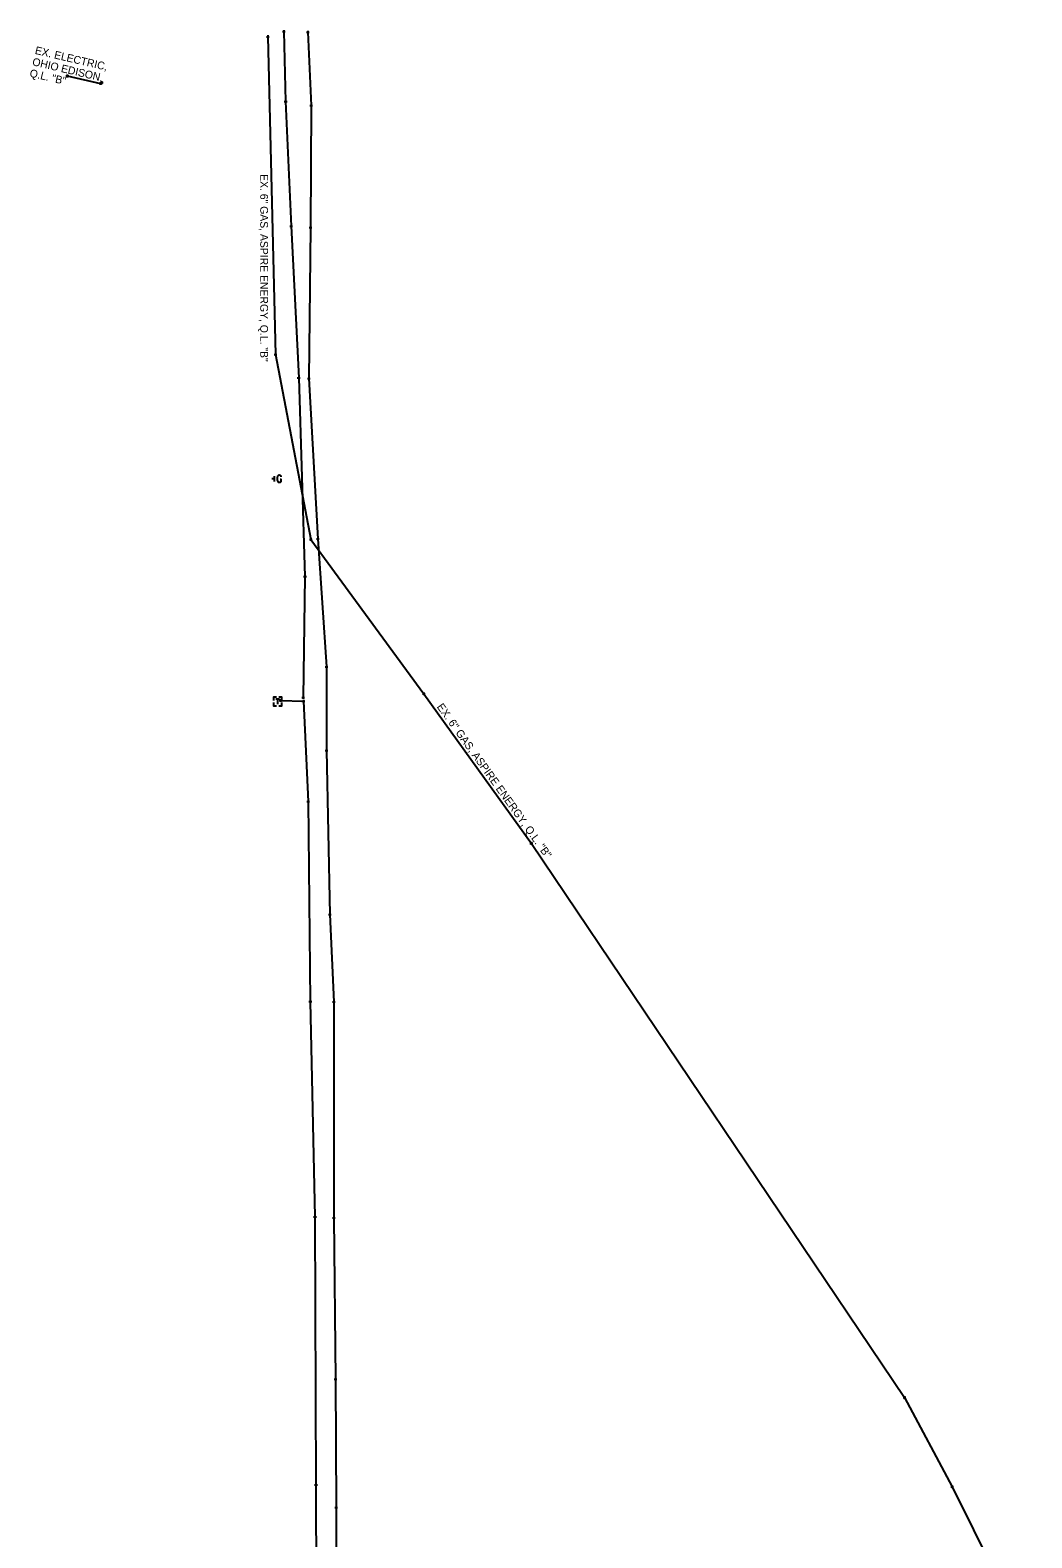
# Model space of a CAD drawing. Extents: x 2046588 to 2048646, y 455919 to 457871.
# Drawn here: x 2047559 to 2047919, y 457329 to 457871 of the extents above; entities that cross this region are included whole.
import ezdxf

# ---------------------------------------------------------------- set-up
doc = ezdxf.new("R2010")
doc.units = 0
for name, color, linetype in [('CM_Corridor_Top_Mesh', 7, 'Continuous'), ('DR_P_Text', 7, 'Continuous'), ('MD_P_Surface_Curb', 7, 'Continuous'), ('PF_P_Grade_Line', 7, 'Continuous'), ('UT_P_Gas', 7, 'Continuous'), ('UT_X_FO', 7, 'Continuous'), ('UT_X_Gas', 7, 'Continuous'), ('UT_X_Overhead_Combined', 7, 'Continuous'), ('UT_X_Overhead_Telecom', 7, 'Continuous')]:
    doc.layers.add(name, color=color, linetype=linetype)

msp = doc.modelspace()

# ---------------------------------------------------------------- linework, layer by layer
at = {"layer": 'CM_Corridor_Top_Mesh'}
for points in [[(2047649.99, 457870.5), (2047650.66, 457845.3), (2047652.68, 457800.52), (2047655.35, 457745.96), (2047657.6, 457674.47), (2047656.94, 457631.01)], [(2047648.82, 457629.87), (2047657.02, 457629.62), (2047658.75, 457593.58), (2047659.52, 457521.71), (2047661.21, 457444.24), (2047661.57, 457347.82), (2047661.76, 457274.75), (2047663.01, 457236.05), (2047662.63, 457177.6), (2047665.24, 457077.73), (2047667.68, 457023.38), (2047665.85, 457013.41)]]:
    msp.add_lwpolyline(points, dxfattribs=at)
at = {"layer": 'PF_P_Grade_Line'}
msp.add_lwpolyline([(2047572.16, 457854.53), (2047584.07, 457851.83), (2047584.5, 457852.13)], dxfattribs=at)
at = {"layer": 'UT_P_Gas'}
for p, q in [((2047647.16, 457630.55), (2047648.46, 457630.55)), ((2047647.81, 457628.55), (2047647.81, 457630.55)), ((2047647.81, 457629.55), (2047647.81, 457629.55))]:
    msp.add_line(p, q, dxfattribs=at)
for points in [[(2047647.41, 457631.05), (2047646.31, 457631.05), (2047646.31, 457629.95)], [(2047646.31, 457629.15), (2047646.31, 457628.05), (2047647.41, 457628.05)], [(2047649.31, 457629.95), (2047649.31, 457631.05), (2047648.21, 457631.05)], [(2047648.21, 457628.05), (2047649.31, 457628.05), (2047649.31, 457629.15)]]:
    msp.add_lwpolyline(points, dxfattribs=at)
at = {"layer": 'UT_X_FO'}
for p, q in [((2047646.6, 457708.65), (2047646.6, 457710.65)), ((2047646.6, 457709.65), (2047645.65, 457709.65))]:
    msp.add_line(p, q, dxfattribs=at)
msp.add_lwpolyline([(2047649.07, 457710.41), (2047649.05, 457710.5), (2047649, 457710.6), (2047648.9, 457710.7), (2047648.76, 457710.82), (2047648.66, 457710.86), (2047648.58, 457710.88), (2047648.46, 457710.9), (2047648.23, 457710.9), (2047648.13, 457710.88), (2047648.07, 457710.86), (2047647.99, 457710.82), (2047647.83, 457710.7), (2047647.74, 457710.56), (2047647.68, 457710.41), (2047647.64, 457710.19), (2047647.6, 457709.87), (2047647.6, 457709.46), (2047647.62, 457709.13), (2047647.7, 457708.87), (2047647.81, 457708.63), (2047647.91, 457708.56), (2047648.03, 457708.48), (2047648.25, 457708.4), (2047648.46, 457708.4), (2047648.68, 457708.44), (2047648.76, 457708.48), (2047648.84, 457708.52), (2047648.92, 457708.59), (2047649, 457708.71), (2047649.07, 457708.89), (2047649.07, 457709.38), (2047648.66, 457709.38)], dxfattribs=at)
at = {"layer": 'UT_X_Gas'}
for p, q in [((2047643.75, 457868.65), (2047644.75, 457868.65)), ((2047644.25, 457869.15), (2047644.25, 457868.15)), ((2047644.25, 457868.65), (2047644.25, 457868.65)), ((2047649.49, 457870.5), (2047650.49, 457870.5)), ((2047649.99, 457871), (2047649.99, 457870)), ((2047649.99, 457870.5), (2047649.99, 457870.5)), ((2047658.1, 457870.23), (2047659.1, 457870.23)), ((2047658.6, 457870.73), (2047658.6, 457869.73)), ((2047658.6, 457870.23), (2047658.6, 457870.23)), ((2047571.66, 457854.53), (2047572.66, 457854.53)), ((2047572.16, 457855.03), (2047572.16, 457854.03)), ((2047572.16, 457854.53), (2047572.16, 457854.53)), ((2047583.57, 457851.83), (2047584.57, 457851.83)), ((2047584, 457852.13), (2047585, 457852.13)), ((2047584.07, 457852.33), (2047584.07, 457851.33)), ((2047584.07, 457851.83), (2047584.07, 457851.83)), ((2047584.5, 457852.63), (2047584.5, 457851.63)), ((2047584.5, 457852.13), (2047584.5, 457852.13)), ((2047650.66, 457845.8), (2047650.66, 457844.8)), ((2047650.16, 457845.3), (2047651.16, 457845.3)), ((2047650.66, 457845.3), (2047650.66, 457845.3)), ((2047659.37, 457843.86), (2047660.37, 457843.86)), ((2047659.87, 457844.36), (2047659.87, 457843.36)), ((2047659.87, 457843.86), (2047659.87, 457843.86)), ((2047652.18, 457800.52), (2047653.18, 457800.52)), ((2047652.68, 457801.02), (2047652.68, 457800.02)), ((2047652.68, 457800.52), (2047652.68, 457800.52)), ((2047659.1, 457800.01), (2047660.1, 457800.01)), ((2047659.6, 457800.51), (2047659.6, 457799.51)), ((2047659.6, 457800.01), (2047659.6, 457800.01)), ((2047646.5, 457754.37), (2047647.5, 457754.37)), ((2047647, 457754.87), (2047647, 457753.87)), ((2047647, 457754.37), (2047647, 457754.37)), ((2047654.85, 457745.96), (2047655.85, 457745.96)), ((2047655.35, 457746.46), (2047655.35, 457745.46)), ((2047655.35, 457745.96), (2047655.35, 457745.96)), ((2047658.48, 457745.74), (2047659.48, 457745.74)), ((2047658.98, 457746.24), (2047658.98, 457745.24)), ((2047658.98, 457745.74), (2047658.98, 457745.74)), ((2047659.75, 457688.32), (2047659.75, 457687.32)), ((2047662.27, 457688.53), (2047662.27, 457687.53)), ((2047659.25, 457687.82), (2047660.25, 457687.82)), ((2047659.75, 457687.82), (2047659.75, 457687.82)), ((2047661.77, 457688.03), (2047662.77, 457688.03)), ((2047662.27, 457688.03), (2047662.27, 457688.03)), ((2047657.1, 457674.47), (2047658.1, 457674.47)), ((2047657.6, 457674.97), (2047657.6, 457673.97)), ((2047657.6, 457674.47), (2047657.6, 457674.47)), ((2047664.86, 457642.02), (2047665.86, 457642.02)), ((2047665.36, 457642.52), (2047665.36, 457641.52)), ((2047665.36, 457642.02), (2047665.36, 457642.02)), ((2047648.32, 457629.87), (2047649.32, 457629.87)), ((2047648.82, 457630.37), (2047648.82, 457629.37)), ((2047648.82, 457629.87), (2047648.82, 457629.87)), ((2047656.44, 457631.01), (2047657.44, 457631.01)), ((2047656.52, 457629.62), (2047657.52, 457629.62)), ((2047656.94, 457631.51), (2047656.94, 457630.51)), ((2047656.94, 457631.01), (2047656.94, 457631.01)), ((2047657.02, 457630.12), (2047657.02, 457629.12)), ((2047657.02, 457629.62), (2047657.02, 457629.62)), ((2047699.82, 457632.34), (2047700.82, 457632.34)), ((2047700.32, 457632.84), (2047700.32, 457631.84)), ((2047700.32, 457632.34), (2047700.32, 457632.34)), ((2047665.36, 457612.48), (2047665.36, 457611.48)), ((2047664.86, 457611.98), (2047665.86, 457611.98)), ((2047665.36, 457611.98), (2047665.36, 457611.98)), ((2047658.25, 457593.58), (2047659.25, 457593.58)), ((2047658.75, 457594.08), (2047658.75, 457593.08)), ((2047658.75, 457593.58), (2047658.75, 457593.58)), ((2047738.49, 457578.52), (2047739.49, 457578.52)), ((2047738.99, 457579.02), (2047738.99, 457578.02)), ((2047738.99, 457578.52), (2047738.99, 457578.52)), ((2047666.08, 457552.89), (2047667.08, 457552.89)), ((2047666.58, 457553.39), (2047666.58, 457552.39)), ((2047666.58, 457552.89), (2047666.58, 457552.89)), ((2047659.02, 457521.71), (2047660.02, 457521.71)), ((2047659.52, 457522.21), (2047659.52, 457521.21)), ((2047659.52, 457521.71), (2047659.52, 457521.71)), ((2047667.51, 457521.56), (2047668.51, 457521.56)), ((2047668.01, 457522.06), (2047668.01, 457521.06)), ((2047668.01, 457521.56), (2047668.01, 457521.56)), ((2047660.71, 457444.24), (2047661.71, 457444.24)), ((2047661.21, 457444.74), (2047661.21, 457443.74)), ((2047661.21, 457444.24), (2047661.21, 457444.24)), ((2047668, 457444.39), (2047668, 457443.39)), ((2047667.5, 457443.89), (2047668.5, 457443.89)), ((2047668, 457443.89), (2047668, 457443.89)), ((2047668.08, 457385.81), (2047669.08, 457385.81)), ((2047668.58, 457386.31), (2047668.58, 457385.31)), ((2047668.58, 457385.81), (2047668.58, 457385.81)), ((2047872.64, 457379.17), (2047873.64, 457379.17)), ((2047873.14, 457379.67), (2047873.14, 457378.67)), ((2047873.14, 457379.17), (2047873.14, 457379.17)), ((2047661.07, 457347.82), (2047662.07, 457347.82)), ((2047661.57, 457348.32), (2047661.57, 457347.32)), ((2047661.57, 457347.82), (2047661.57, 457347.82)), ((2047889.77, 457347.12), (2047890.77, 457347.12)), ((2047890.27, 457347.62), (2047890.27, 457346.62)), ((2047890.27, 457347.12), (2047890.27, 457347.12)), ((2047668.33, 457339.7), (2047669.33, 457339.7)), ((2047668.83, 457340.2), (2047668.83, 457339.2)), ((2047668.83, 457339.7), (2047668.83, 457339.7))]:
    msp.add_line(p, q, dxfattribs=at)
at = {"layer": 'UT_X_Overhead_Combined'}
msp.add_lwpolyline([(2047658.6, 457870.23), (2047659.87, 457843.86), (2047659.6, 457800.01), (2047658.98, 457745.74), (2047662.27, 457688.03), (2047665.36, 457642.02), (2047665.36, 457611.98), (2047666.58, 457552.89), (2047668.01, 457521.56), (2047668, 457443.89), (2047668.58, 457385.81), (2047668.83, 457339.7), (2047668.78, 457275.83), (2047670.9, 457219.79), (2047672.29, 457188.61), (2047673.09, 457121.54), (2047675.09, 457078.33), (2047679.08, 457014.24), (2047677.13, 456991.2), (2047677.25, 456977.91), (2047672.71, 456954.72)], dxfattribs=at)
at = {"layer": 'UT_X_Overhead_Telecom'}
for points in [[(2047644.25, 457868.65), (2047647, 457754.37), (2047659.75, 457687.82), (2047700.32, 457632.34), (2047738.99, 457578.52), (2047873.14, 457379.17)], [(2047873.14, 457379.17), (2047890.27, 457347.12), (2047905.65, 457316.11), (2047914.53, 457280.99), (2047918.31, 457250.15), (2047918.91, 457206.27), (2047918.04, 457168.01), (2047916.51, 457112.29)]]:
    msp.add_lwpolyline(points, dxfattribs=at)

# ---------------------------------------------------------------- texts
at = {"layer": 'DR_P_Text'}
for s, p in [('EX. ELECTRIC, ', (2047560.34, 457862.51)), ('Q.L. "B"', (2047558.42, 457854.33)), ('OHIO EDISON,', (2047559.38, 457858.42))]:
    msp.add_text(s, height=2.8, rotation=346.785, dxfattribs=at).set_placement(p)
at = {"layer": 'MD_P_Surface_Curb'}
for rotation, p in [(270, (2047641.53, 457819.22)), (305.6994, (2047704.87, 457627.63))]:
    msp.add_text('EX. 6" GAS, ASPIRE ENERGY, Q.L. "B"', height=2.8, rotation=rotation, dxfattribs=at).set_placement(p)

doc.saveas('drawing.dxf')
